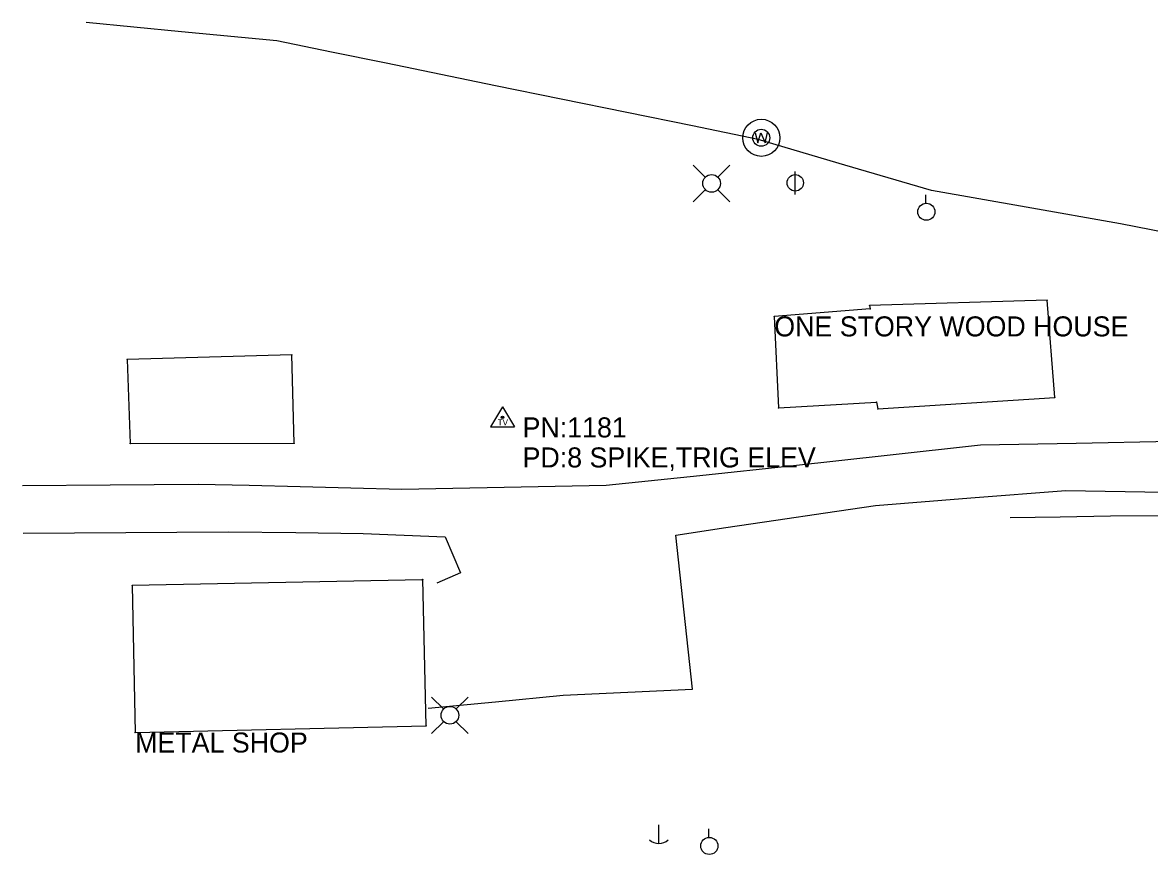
# Model space of a CAD drawing. Extents: x 1445297 to 1476720, y 2042269 to 2057889.
# Drawn here: x 1445296.9 to 1445578.3, y 2053337.4 to 2053545.2 of the extents above; entities that cross this region are included whole.
import ezdxf

# ---------------------------------------------------------------- set-up
doc = ezdxf.new("R2010")
doc.units = 0
for name, color, linetype in [('S_BUILDING', 7, 'Continuous'), ('S_BUILDING_ANNOT', 7, 'Continuous'), ('S_DITCHLINE', 7, 'Continuous'), ('S_DRIVEWAY', 7, 'Continuous'), ('S_SECONDARY_CTL', 7, 'Continuous'), ('S_SECONDARY_CTL_ANNOT', 7, 'Continuous'), ('S_STR_PT_SYM', 7, 'Continuous'), ('S_UTILITY_POLE', 7, 'Continuous'), ('S_WATER_WELL', 7, 'Continuous')]:
    doc.layers.add(name, color=color, linetype=linetype)

msp = doc.modelspace()

# ---------------------------------------------------------------- linework, layer by layer
at = {"layer": 'S_BUILDING'}
for p, q in [((1445508.54, 2053473.7), (1445484.59, 2053471.84)), ((1445552.74, 2053475.86), (1445508.38, 2053474.6)), ((1445508.38, 2053474.6), (1445508.54, 2053473.7)), ((1445554.6, 2053451.55), (1445552.74, 2053475.86)), ((1445484.59, 2053471.84), (1445485.65, 2053448.96)), ((1445364.17, 2053462.24), (1445323.06, 2053461.1)), ((1445364.78, 2053440.15), (1445364.17, 2053462.24)), ((1445323.06, 2053461.1), (1445323.82, 2053440.09)), ((1445510.44, 2053448.74), (1445554.6, 2053451.55)), ((1445485.65, 2053448.96), (1445510.09, 2053450.41)), ((1445510.09, 2053450.41), (1445510.44, 2053448.74)), ((1445323.82, 2053440.09), (1445364.78, 2053440.15)), ((1445396.7, 2053406.02), (1445324.34, 2053404.65)), ((1445396.83, 2053406.16), (1445396.7, 2053406.02)), ((1445397.71, 2053369.59), (1445396.83, 2053406.16)), ((1445324.34, 2053404.65), (1445325.04, 2053367.9)), ((1445325.04, 2053367.9), (1445397.71, 2053369.59))]:
    msp.add_line(p, q, dxfattribs=at)
at = {"layer": 'S_DITCHLINE'}
for points in [[(1445615.87, 2053456.8), (1445616.26, 2053471.68), (1445608.56, 2053484.64), (1445602.41, 2053488.81), (1445586.73, 2053491.91), (1445571.06, 2053495), (1445547.47, 2053499.13), (1445523.88, 2053503.25), (1445502.22, 2053509.65), (1445480.56, 2053516.06), (1445464.18, 2053519.41), (1445447.8, 2053522.76), (1445431.41, 2053526.11), (1445415.03, 2053529.45), (1445401.39, 2053532.26), (1445387.74, 2053535.07), (1445374.09, 2053537.87), (1445360.44, 2053540.68), (1445336.65, 2053542.96), (1445312.85, 2053545.24)], [(1445614.92, 2053416.79), (1445612.09, 2053422.21), (1445590.3, 2053422.05), (1445568.5, 2053421.9), (1445555.99, 2053421.71), (1445543.49, 2053421.52)]]:
    msp.add_lwpolyline(points, dxfattribs=at)
at = {"layer": 'S_DRIVEWAY'}
for points in [[(1445661.61, 2053447.87), (1445653.76, 2053443.33), (1445636.84, 2053442.4), (1445619.91, 2053441.46), (1445601.9, 2053441.02), (1445583.88, 2053440.57), (1445559.97, 2053440.13), (1445536.07, 2053439.69), (1445512.74, 2053437.08), (1445489.41, 2053434.47), (1445466.04, 2053432.05), (1445442.66, 2053429.63), (1445429.9, 2053429.37), (1445417.14, 2053429.11), (1445404.39, 2053428.85), (1445391.63, 2053428.58), (1445378.91, 2053428.91), (1445366.2, 2053429.24), (1445353.49, 2053429.56), (1445340.77, 2053429.89), (1445318.85, 2053429.7), (1445296.93, 2053429.52)], [(1445398.2, 2053374.01), (1445415.04, 2053375.6), (1445431.88, 2053377.2), (1445448.05, 2053377.97), (1445464.22, 2053378.74), (1445462.13, 2053397.98), (1445460.04, 2053417.23), (1445472.5, 2053419.07), (1445484.95, 2053420.91), (1445497.4, 2053422.75), (1445509.86, 2053424.59), (1445533.64, 2053426.48), (1445557.42, 2053428.37), (1445582.02, 2053427.95), (1445606.63, 2053427.54), (1445623.57, 2053426.72), (1445640.51, 2053425.89), (1445654.34, 2053419.81), (1445664.64, 2053411.89)], [(1445297.09, 2053417.72), (1445309.89, 2053417.79), (1445322.68, 2053417.87), (1445335.47, 2053417.94), (1445348.26, 2053418.01), (1445365.12, 2053417.83), (1445381.98, 2053417.64), (1445402.4, 2053416.8), (1445406.23, 2053407.75), (1445400.33, 2053405.23)]]:
    msp.add_lwpolyline(points, dxfattribs=at)
at = {"layer": 'S_SECONDARY_CTL'}
for p, q in [((1445416.76, 2053449.22), (1445413.75, 2053444.27)), ((1445416.76, 2053449.22), (1445419.71, 2053444.27)), ((1445413.75, 2053444.27), (1445419.71, 2053444.27))]:
    msp.add_line(p, q, dxfattribs=at)
for radius in [0.311, 0.183, 0.103]:
    msp.add_circle((1445416.76, 2053446.61), radius, dxfattribs=at)
at = {"layer": 'S_STR_PT_SYM'}
for points in [[(1445508.38, 2053474.6), (1445508.38, 2053474.65), (1445508.38, 2053474.6), (1445508.33, 2053474.6), (1445508.38, 2053474.6), (1445508.38, 2053474.55), (1445508.38, 2053474.6), (1445508.43, 2053474.6)], [(1445508.54, 2053473.7), (1445508.54, 2053473.75), (1445508.54, 2053473.7), (1445508.49, 2053473.7), (1445508.54, 2053473.7), (1445508.54, 2053473.65), (1445508.54, 2053473.7), (1445508.59, 2053473.7)], [(1445552.74, 2053475.86), (1445552.74, 2053475.91), (1445552.74, 2053475.86), (1445552.69, 2053475.86), (1445552.74, 2053475.86), (1445552.74, 2053475.81), (1445552.74, 2053475.86), (1445552.79, 2053475.86)], [(1445484.59, 2053471.84), (1445484.59, 2053471.89), (1445484.59, 2053471.84), (1445484.54, 2053471.84), (1445484.59, 2053471.84), (1445484.59, 2053471.79), (1445484.59, 2053471.84), (1445484.64, 2053471.84)], [(1445364.17, 2053462.24), (1445364.17, 2053462.29), (1445364.17, 2053462.24), (1445364.12, 2053462.24), (1445364.17, 2053462.24), (1445364.17, 2053462.19), (1445364.17, 2053462.24), (1445364.22, 2053462.24)], [(1445323.06, 2053461.1), (1445323.06, 2053461.15), (1445323.06, 2053461.1), (1445323.01, 2053461.1), (1445323.06, 2053461.1), (1445323.06, 2053461.05), (1445323.06, 2053461.1), (1445323.11, 2053461.1)], [(1445554.6, 2053451.55), (1445554.6, 2053451.6), (1445554.6, 2053451.55), (1445554.55, 2053451.55), (1445554.6, 2053451.55), (1445554.6, 2053451.5), (1445554.6, 2053451.55), (1445554.65, 2053451.55)], [(1445485.65, 2053448.96), (1445485.65, 2053449.01), (1445485.65, 2053448.96), (1445485.6, 2053448.96), (1445485.65, 2053448.96), (1445485.65, 2053448.91), (1445485.65, 2053448.96), (1445485.7, 2053448.96)], [(1445510.09, 2053450.41), (1445510.09, 2053450.46), (1445510.09, 2053450.41), (1445510.04, 2053450.41), (1445510.09, 2053450.41), (1445510.09, 2053450.36), (1445510.09, 2053450.41), (1445510.14, 2053450.41)], [(1445510.44, 2053448.74), (1445510.44, 2053448.79), (1445510.44, 2053448.74), (1445510.39, 2053448.74), (1445510.44, 2053448.74), (1445510.44, 2053448.69), (1445510.44, 2053448.74), (1445510.49, 2053448.74)], [(1445323.82, 2053440.09), (1445323.82, 2053440.14), (1445323.82, 2053440.09), (1445323.77, 2053440.09), (1445323.82, 2053440.09), (1445323.82, 2053440.04), (1445323.82, 2053440.09), (1445323.87, 2053440.09)], [(1445364.78, 2053440.15), (1445364.78, 2053440.2), (1445364.78, 2053440.15), (1445364.73, 2053440.15), (1445364.78, 2053440.15), (1445364.78, 2053440.1), (1445364.78, 2053440.15), (1445364.83, 2053440.15)], [(1445396.7, 2053406.02), (1445396.7, 2053406.07), (1445396.7, 2053406.02), (1445396.65, 2053406.02), (1445396.7, 2053406.02), (1445396.7, 2053405.97), (1445396.7, 2053406.02), (1445396.75, 2053406.02)], [(1445396.83, 2053406.16), (1445396.83, 2053406.21), (1445396.83, 2053406.16), (1445396.78, 2053406.16), (1445396.83, 2053406.16), (1445396.83, 2053406.11), (1445396.83, 2053406.16), (1445396.88, 2053406.16)], [(1445324.34, 2053404.65), (1445324.34, 2053404.7), (1445324.34, 2053404.65), (1445324.29, 2053404.65), (1445324.34, 2053404.65), (1445324.34, 2053404.6), (1445324.34, 2053404.65), (1445324.39, 2053404.65)], [(1445397.71, 2053369.59), (1445397.71, 2053369.64), (1445397.71, 2053369.59), (1445397.66, 2053369.59), (1445397.71, 2053369.59), (1445397.71, 2053369.54), (1445397.71, 2053369.59), (1445397.76, 2053369.59)], [(1445325.04, 2053367.9), (1445325.04, 2053367.95), (1445325.04, 2053367.9), (1445324.99, 2053367.9), (1445325.04, 2053367.9), (1445325.04, 2053367.85), (1445325.04, 2053367.9), (1445325.09, 2053367.9)]]:
    msp.add_lwpolyline(points, dxfattribs=at)
at = {"layer": 'S_UTILITY_POLE'}
for p, q in [((1445467.35, 2053506.65), (1445464.37, 2053509.63)), ((1445470.53, 2053506.65), (1445473.51, 2053509.63)), ((1445489.83, 2053502.27), (1445489.83, 2053508.06)), ((1445467.35, 2053503.47), (1445464.37, 2053500.49)), ((1445470.53, 2053503.47), (1445473.51, 2053500.49)), ((1445522.44, 2053500.11), (1445522.44, 2053502.22)), ((1445402.02, 2053373.78), (1445399.04, 2053376.76)), ((1445405.2, 2053373.78), (1445408.19, 2053376.76)), ((1445402.02, 2053370.6), (1445399.04, 2053367.62)), ((1445405.2, 2053370.6), (1445408.19, 2053367.62)), ((1445455.73, 2053344.87), (1445455.73, 2053340.14)), ((1445468.26, 2053341.7), (1445468.26, 2053343.81))]:
    msp.add_line(p, q, dxfattribs=at)
for centre, radius in [((1445468.95, 2053505.07), 2.21), ((1445489.83, 2053505.2), 2.05), ((1445522.56, 2053497.97), 2.13), ((1445403.62, 2053372.2), 2.21), ((1445468.38, 2053339.56), 2.13)]:
    msp.add_circle(centre, radius, dxfattribs=at)
msp.add_arc((1445455.79, 2053343.57), 3.41, 226.3972, 313.6028, dxfattribs=at)
at = {"layer": 'S_WATER_WELL'}
for p, q in [((1445479.81, 2053517.71), (1445480.46, 2053515.23)), ((1445480.46, 2053515.23), (1445481.28, 2053517.71)), ((1445481.28, 2053517.71), (1445482.32, 2053515.23)), ((1445482.32, 2053515.23), (1445482.91, 2053517.75))]:
    msp.add_line(p, q, dxfattribs=at)
for centre, radius in [((1445481.37, 2053516.45), 4.63), ((1445481.34, 2053516.45), 2.13)]:
    msp.add_circle(centre, radius, dxfattribs=at)

# ---------------------------------------------------------------- texts
at = {"layer": 'S_BUILDING_ANNOT'}
for s, p in [('ONE STORY WOOD HOUSE', (1445484.59, 2053466.84)), ('METAL SHOP', (1445325.04, 2053362.9))]:
    msp.add_text(s, height=5, dxfattribs=at).set_placement(p)
at = {"layer": 'S_SECONDARY_CTL'}
msp.add_text('TV', height=1.5, dxfattribs=at).set_placement((1445415.55, 2053444.6))
at = {"layer": 'S_SECONDARY_CTL_ANNOT'}
for s, p in [('PN:1181', (1445421.76, 2053441.61)), ('PD:8 SPIKE,TRIG ELEV', (1445421.76, 2053434.11))]:
    msp.add_text(s, height=5, dxfattribs=at).set_placement(p)

doc.saveas('drawing.dxf')
